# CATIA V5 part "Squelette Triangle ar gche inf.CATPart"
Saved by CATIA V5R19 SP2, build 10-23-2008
Part number: Squelette Triangle ar gche inf
Bounding box of the stored display mesh (mm): x 296.225 to 352.222, y -266.234 to -175.158, z 24.566 to 47.84
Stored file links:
  D:\Mes Documents\ressource\CATIA\Ensemble Catia\Voiture_Telecommmande\SchemaCinematiqueFinal\Squelette Triangle ar gche inf.CATPart
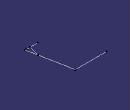
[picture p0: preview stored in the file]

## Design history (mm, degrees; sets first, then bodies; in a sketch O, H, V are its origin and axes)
AxisSystem1: origin (0, 0, 0), X (1, 0, 0), Y (0, 1, 0), Z (0, 0, 1)
Body1 (main body)
  Line1 to Line5: stored without definition
  Point1 to Point3: stored without definition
